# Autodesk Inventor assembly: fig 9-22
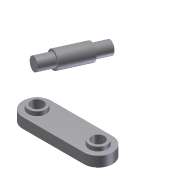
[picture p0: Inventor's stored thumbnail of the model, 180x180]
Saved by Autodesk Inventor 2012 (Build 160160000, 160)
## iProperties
Shininess: 64.0
Length Units: 11269
Angle Units: 11279
Time Units: 11290
Mass Units: 11283
Length Display Precision: 3
Angle Display Precision: 2
Created: 2002-01
Part Number: fig 9-22
Document SubType Name: Assembly
Designer: ***
Density: 0.0
Volumn: 0.0
Area: 0.0
PropertySet Name: Model Information
Control State: 0
Master: False
Checked Out: False
Author: ***
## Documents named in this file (3)
- C:\Users\CadCim\Documents\SAILESH\inventor-2011-fact-prt\c09_inv_2011-prt\c09_inv_2012_prt\fig 9-22.iam
- C:\Users\CadCim\Documents\SAILESH\inventor-2011-fact-prt\c09_inv_2011-prt\c09_inv_2012_prt\Part5.ipt
- C:\Users\CadCim\Documents\SAILESH\inventor-2011-fact-prt\c09_inv_2011-prt\c09_inv_2012_prt\Part6.ipt
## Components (2 placed, 2 different names)
1. Part5:1
2. Part6:1
